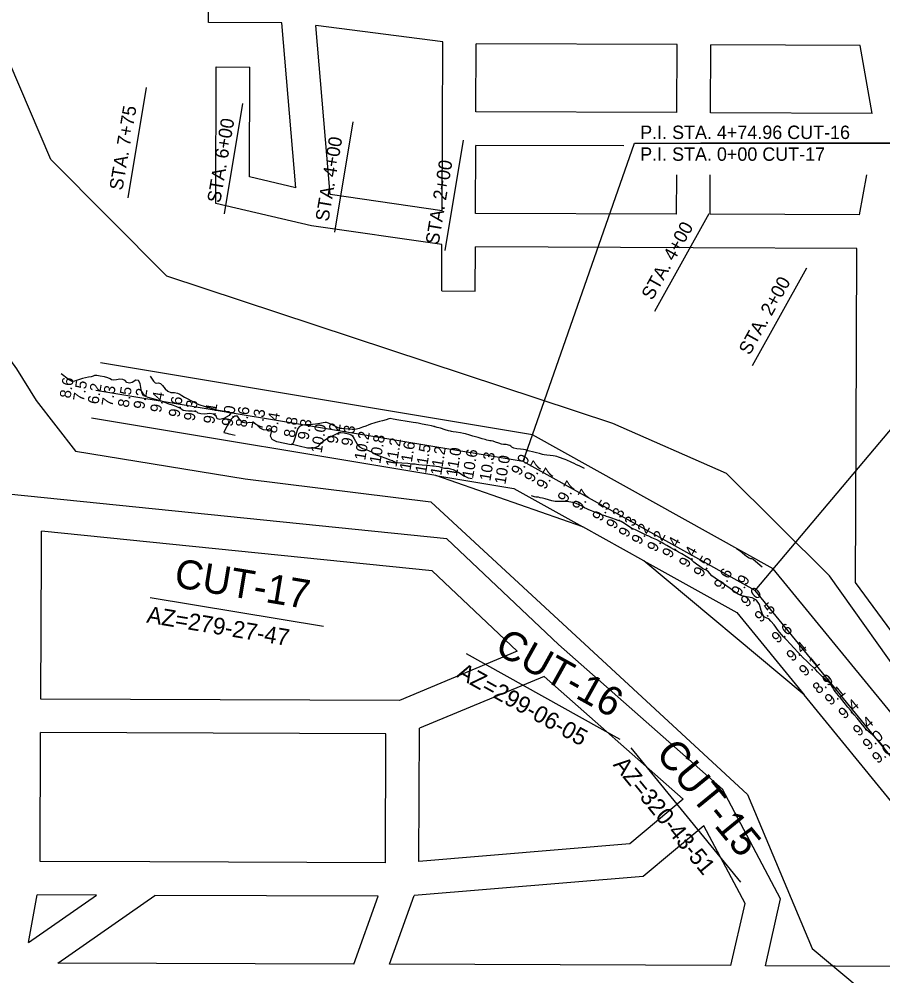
# Model space of a CAD drawing. Extents: x 497696 to 505896, y 1319278 to 1325078.
# Drawn here: x 500990 to 502536, y 1320945 to 1322658 of the extents above; entities that cross this region are included whole.
import ezdxf

# ---------------------------------------------------------------- set-up
doc = ezdxf.new("R2010")
doc.units = 0
for name, color, linetype in [('Level 1', 7, 'Continuous'), ('Level 32', 7, 'Continuous'), ('Level 49', 7, 'Continuous'), ('Level 5', 7, 'Continuous'), ('Level 50', 7, 'Continuous'), ('Level 51', 7, 'Continuous'), ('Level 56', 7, 'Continuous'), ('Level 6', 7, 'Continuous')]:
    doc.layers.add(name, color=color, linetype=linetype)

msp = doc.modelspace()

# ---------------------------------------------------------------- linework, layer by layer
at = {"layer": 'Level 1'}
for points in [[(501212.5, 1321984.1), (501210.3, 1321988.2), (501208.4, 1321995.4), (501206.7, 1322005.8), (501203.5, 1322011.4), (501198.8, 1322012.1), (501192.6, 1322008), (501187.4, 1322006.5), (501183.1, 1322007.6), (501179.9, 1322011.3), (501175.6, 1322013.3), (501170.4, 1322013.6), (501164.2, 1322012.3), (501159.2, 1322012), (501155.5, 1322012.6), (501152.9, 1322014.4), (501148.7, 1322016.1), (501142.8, 1322017.7), (501135.1, 1322019.4), (501129.2, 1322020.2), (501124.9, 1322020.2), (501122.4, 1322019.2), (501118.9, 1322018.2), (501114.4, 1322017.2), (501108.9, 1322016), (501103.5, 1322014.7), (501098.2, 1322013.1), (501092.9, 1322011.4), (501089, 1322010.2), (501086.4, 1322009.5), (501085.2, 1322009.4), (501082.3, 1322010.9), (501077.7, 1322014), (501065.1, 1322023.3)], [(501224.6, 1322019.1), (501230.4, 1322010), (501233.4, 1322007.3), (501236.4, 1322006.4), (501239.4, 1322007.5), (501242.9, 1322006.1), (501246.9, 1322002.5), (501251.3, 1321996.5), (501256.2, 1321992.4), (501261.8, 1321990.2), (501267.9, 1321989.9), (501273.3, 1321988.8), (501277.8, 1321987), (501281.5, 1321984.4), (501286.2, 1321981.5), (501291.8, 1321978.4), (501298.3, 1321975), (501303.3, 1321972.5), (501306.7, 1321970.7), (501308.6, 1321969.7), (501313.4, 1321968.1), (501321, 1321965.7), (501331.4, 1321962.6), (501338.5, 1321960.5), (501342.3, 1321959.3), (501342.8, 1321958.9), (501346.8, 1321958.2), (501354.2, 1321957.1), (501365.1, 1321955.6), (501369.1, 1321952.8), (501366.2, 1321948.8), (501356.4, 1321943.4), (501349.2, 1321941.5), (501344.6, 1321943), (501342.6, 1321947.8), (501338.2, 1321950.9), (501331.4, 1321952.1), (501322.1, 1321951.4), (501315.2, 1321951.6), (501310.7, 1321952.7), (501308.5, 1321954.5), (501304.8, 1321955.8), (501299.6, 1321956.4), (501292.9, 1321956.5), (501287.6, 1321957), (501283.8, 1321957.9), (501281.4, 1321959.3), (501279.4, 1321960.5), (501277.7, 1321961.7), (501276.5, 1321962.7), (501272.6, 1321964.4), (501266.1, 1321966.7), (501257, 1321969.7), (501250.7, 1321971.8), (501247.2, 1321973.2), (501246.4, 1321973.8), (501242.9, 1321975), (501236.5, 1321976.9), (501227.4, 1321979.4), (501221.2, 1321981.1), (501217.9, 1321982.1), (501217.6, 1321982.3), (501216.6, 1321982.7), (501214.9, 1321983.3), (501212.5, 1321984.1)], [(501476.8, 1321896.1), (501451.1, 1321901.6), (501443.1, 1321906), (501440.1, 1321911.9), (501442, 1321919.5), (501441.4, 1321923.8), (501438.5, 1321924.8), (501433.1, 1321922.5), (501427.5, 1321923), (501421.5, 1321926.2), (501415.3, 1321932), (501409, 1321935.5), (501402.7, 1321936.5), (501396.4, 1321935), (501390.6, 1321936.3), (501385.4, 1321940.4), (501380.7, 1321947.3), (501375.4, 1321947.8), (501369.3, 1321942.2), (501362.6, 1321930.2), (501358.3, 1321922.2), (501356.5, 1321918.1), (501357.1, 1321918), (501358.8, 1321917.5), (501361.5, 1321916.9), (501365.3, 1321916), (501368.7, 1321915.2), (501371.6, 1321914.6), (501376.6, 1321913.5)], [(501744, 1321925.8), (501738.2, 1321927.5), (501734.9, 1321928.5), (501734.2, 1321928.7), (501733.5, 1321928.9), (501732.8, 1321929.1), (501732.1, 1321929.3), (501728.3, 1321930.1), (501721.3, 1321931.5), (501711.1, 1321933.5), (501704.2, 1321934.9), (501700.6, 1321935.5), (501700.2, 1321935.5), (501695, 1321936.4), (501684.8, 1321938.1), (501669.9, 1321940.6), (501659.7, 1321942.3), (501654.4, 1321943.1), (501654, 1321943.1), (501651.5, 1321942.5), (501647, 1321941.2), (501640.5, 1321939.2), (501635.2, 1321937.8), (501631.1, 1321936.8), (501628.2, 1321936.3), (501624.7, 1321935.3), (501620.7, 1321933.8), (501616.1, 1321931.9), (501610.8, 1321929.8), (501604.9, 1321927.7), (501598.4, 1321925.5), (501593.7, 1321924.1), (501590.6, 1321923.5), (501589.4, 1321923.6), (501586, 1321923.9), (501580.4, 1321924.3), (501572.7, 1321925), (501567.4, 1321925.3), (501564.4, 1321925.4), (501563.8, 1321925.2), (501561, 1321926.4), (501556.1, 1321928.9), (501549, 1321932.7), (501543.6, 1321935.2), (501540, 1321936.4), (501538, 1321936.1), (501534.1, 1321935.6), (501528.4, 1321934.7), (501520.7, 1321933.5), (501515.4, 1321932.7), (501512.4, 1321932.3), (501511.7, 1321932.3), (501509.7, 1321932.3), (501506.4, 1321932.1), (501501.7, 1321931.8), (501497.7, 1321931.2), (501494.4, 1321930.4), (501491.8, 1321929.3), (501489.1, 1321925.2), (501486.3, 1321918.1), (501483.5, 1321907.9), (501481.1, 1321901.1), (501479.2, 1321897.7), (501477.7, 1321897.7), (501481.7, 1321896.6)], [(501481.7, 1321896.6), (501491.2, 1321894.4), (501506.2, 1321891.1), (501517.8, 1321890.9), (501526, 1321893.8), (501530.8, 1321899.7), (501536.5, 1321904.8), (501543.3, 1321909), (501551, 1321912.5), (501556.7, 1321915.1), (501560.4, 1321917.1), (501562, 1321918.2), (501565.7, 1321918.4), (501571.5, 1321917.7), (501579.3, 1321916.1), (501584.6, 1321914.3), (501587.5, 1321912.3), (501588, 1321910.1), (501589.4, 1321906.9), (501591.8, 1321902.6), (501595.1, 1321897.2), (501599.5, 1321892.9), (501604.9, 1321889.7), (501611.3, 1321887.6), (501616.5, 1321885.5), (501620.5, 1321883.5), (501623.3, 1321881.4), (501628.5, 1321878.9), (501636.1, 1321875.8), (501646.2, 1321872.2), (501653.5, 1321869.6), (501658, 1321867.9), (501659.6, 1321867.1), (501661, 1321866.5), (501662.2, 1321865.8), (501663.2, 1321865.3), (501667.5, 1321864.7), (501675, 1321863.9), (501685.8, 1321863.1), (501693.7, 1321862.4), (501698.8, 1321861.9), (501701.1, 1321861.6), (501705.2, 1321861.1), (501711.1, 1321860.5), (501718.9, 1321859.7), (501725.1, 1321859.1), (501729.7, 1321858.8), (501732.7, 1321858.8), (501736.6, 1321858.3), (501741.3, 1321857.2), (501746.8, 1321855.7), (501751.5, 1321854.7), (501755.2, 1321854.2), (501758.1, 1321854.3), (501761.9, 1321853.5), (501766.6, 1321851.8), (501772.2, 1321849.2), (501777.2, 1321846.5), (501781.8, 1321843.8), (501785.9, 1321840.9), (501789.9, 1321838.8), (501793.7, 1321837.4), (501801.1, 1321835.9)], [(502002.1, 1321854.1), (501992.4, 1321858.4), (501987.8, 1321860.5), (501983.4, 1321862.5), (501979.2, 1321864.5), (501975.6, 1321866.1), (501972.6, 1321867.4), (501970.2, 1321868.5), (501967.2, 1321869.7), (501963.5, 1321871.1), (501959.2, 1321872.8), (501955.5, 1321874.2), (501952.3, 1321875.3), (501949.7, 1321876), (501945.8, 1321876.7), (501940.7, 1321877.4), (501934.4, 1321878), (501929.7, 1321878.6), (501926.6, 1321879.2), (501925.1, 1321879.6), (501921.6, 1321880.5), (501916.2, 1321881.8), (501908.7, 1321883.6), (501903.7, 1321884.8), (501901, 1321885.5), (501900.6, 1321885.7), (501899.7, 1321886), (501898.3, 1321886.5), (501896.2, 1321887.1), (501892.6, 1321887.8), (501887.4, 1321888.5), (501880.7, 1321889.3), (501875.5, 1321890.4), (501872, 1321891.8), (501870, 1321893.6), (501868, 1321894.9), (501865.9, 1321895.9), (501863.9, 1321896.5), (501861.7, 1321896.8), (501859.3, 1321897), (501856.8, 1321896.9), (501853.2, 1321897.6), (501848.6, 1321899), (501842.8, 1321901.1), (501838.2, 1321902.6), (501834.7, 1321903.3), (501832.4, 1321903.4), (501829.9, 1321903.8), (501827.1, 1321904.5), (501824, 1321905.5), (501818.8, 1321907.1), (501811.5, 1321909.3), (501802, 1321912), (501795, 1321914), (501790.6, 1321915.3), (501788.7, 1321916), (501785.1, 1321916.7), (501779.7, 1321917.7), (501772.4, 1321918.8), (501767.1, 1321919.6), (501763.7, 1321920.2), (501762.2, 1321920.5), (501758.4, 1321921.5), (501752.3, 1321923.3), (501744, 1321925.8)], [(502105.1, 1321738.3), (502098.2, 1321741.5), (502093.2, 1321743.8), (502090, 1321745.1), (502088.7, 1321745.5), (502085.8, 1321747.1), (502081.3, 1321749.9), (502075.3, 1321754), (502070.7, 1321757), (502067.5, 1321758.8), (502065.8, 1321759.4), (502062.4, 1321760.7), (502057.4, 1321762.4), (502050.7, 1321764.8), (502045.4, 1321766.7), (502041.4, 1321768), (502038.7, 1321768.9), (502034.4, 1321770.4), (502028.4, 1321772.7), (502020.7, 1321775.6), (502014.4, 1321778.1), (502009.5, 1321780.1), (502005.9, 1321781.7), (502001.9, 1321783.7), (501997.5, 1321786.1), (501992.6, 1321789), (501987, 1321791.2), (501980.8, 1321793), (501973.8, 1321794.2), (501967.3, 1321794.9), (501961.1, 1321795), (501955.2, 1321794.5), (501949.3, 1321794.9), (501943.3, 1321796), (501937.2, 1321797.9), (501931.7, 1321799.4), (501926.9, 1321800.7), (501922.7, 1321801.6), (501919.6, 1321802.3), (501917.5, 1321802.6), (501916.4, 1321802.5), (501914.8, 1321802.8), (501912.5, 1321803.3), (501906.8, 1321804.8)], [(502383.2, 1321525.5), (502377.5, 1321531.7), (502369.7, 1321540.4), (502363.9, 1321546.7), (502360.1, 1321550.7), (502358.3, 1321552.4), (502354.5, 1321556.9), (502348.8, 1321564), (502341.1, 1321573.9), (502335.4, 1321580.7), (502331.7, 1321584.5), (502330, 1321585.3), (502328.1, 1321586.1), (502326, 1321587), (502323.8, 1321587.8), (502321.2, 1321591.9), (502318.4, 1321599.4), (502315.2, 1321610.3), (502309.7, 1321618), (502301.9, 1321622.5), (502291.7, 1321623.9), (502283.3, 1321626), (502276.7, 1321628.6), (502271.9, 1321631.8), (502267.9, 1321634.6), (502264.9, 1321636.9), (502262.7, 1321638.7), (502260.1, 1321640.6), (502257.3, 1321642.8), (502254.1, 1321645), (502249.4, 1321648.2), (502243.3, 1321652.4), (502235.8, 1321657.5), (502230, 1321661.9), (502226.1, 1321665.6), (502223.9, 1321668.7), (502221.6, 1321670.9), (502219.2, 1321672.4), (502216.7, 1321673), (502213, 1321674.9), (502208.2, 1321678.2), (502202.3, 1321682.8), (502197.8, 1321686.3), (502194.8, 1321688.9), (502193.3, 1321690.4), (502189.7, 1321692.9), (502183.9, 1321696.4), (502175.9, 1321701), (502170, 1321704.2), (502166.4, 1321706.3), (502165, 1321707), (502161.6, 1321708.9), (502156.3, 1321712), (502149.1, 1321716.2), (502144, 1321719.2), (502141, 1321721), (502140.2, 1321721.5), (502136.9, 1321723.1), (502131.1, 1321725.9), (502122.7, 1321729.8), (502116.8, 1321732.5), (502113.5, 1321734.1), (502112.7, 1321734.6), (502109.9, 1321735.9), (502105.1, 1321738.3)], [(502274.1, 1321710.3), (502277.3, 1321708.3), (502278.8, 1321707.3), (502280, 1321706.3), (502281, 1321705.4), (502282.1, 1321704.5), (502283.3, 1321703.5), (502284.7, 1321702.5), (502286.1, 1321701.4), (502287.6, 1321700.2), (502289.1, 1321698.8), (502291.1, 1321697.3), (502293.6, 1321695.7), (502296.6, 1321693.9), (502298.9, 1321692.8), (502300.5, 1321692.4), (502301.4, 1321692.8), (502304, 1321691.2), (502308.2, 1321687.9), (502319.8, 1321677.5)], [(502541.4, 1321349.1), (502535.7, 1321357.1), (502529.7, 1321364.5), (502523.3, 1321371.2), (502516.5, 1321377.4), (502511.7, 1321381.7), (502508.9, 1321384.2), (502508.1, 1321384.8), (502507.2, 1321385.6), (502506.4, 1321386.6), (502505.6, 1321387.7), (502502.5, 1321391.4), (502497.2, 1321397.8), (502489.7, 1321406.7), (502484.5, 1321413), (502481.5, 1321416.6), (502480.8, 1321417.6), (502478.1, 1321420.9), (502473.5, 1321426.6), (502466.9, 1321434.7), (502462.4, 1321440.2), (502460, 1321443.1), (502459.8, 1321443.4), (502458.6, 1321444.8), (502456.5, 1321447.3), (502453.5, 1321451), (502450.8, 1321454.6), (502448.2, 1321458.4), (502445.8, 1321462.2), (502444.1, 1321465.1), (502443, 1321466.9), (502442.5, 1321467.9), (502440.6, 1321469.8), (502437.2, 1321472.7), (502432.4, 1321476.7), (502427.7, 1321480.9), (502423.2, 1321485.3), (502418.9, 1321490), (502416, 1321493.2), (502414.4, 1321494.9), (502414.1, 1321495.1), (502411.5, 1321497.6), (502406.5, 1321502.4), (502399.2, 1321509.5), (502394, 1321514.5), (502391, 1321517.4), (502390.2, 1321518.3), (502389.2, 1321519.3), (502388, 1321520.4), (502386.7, 1321521.8), (502383.2, 1321525.5)]]:
    msp.add_lwpolyline(points, dxfattribs=at)
at = {"layer": 'Level 32'}
for p, q in [((501328.7, 1322652.4), (501330.1, 1323009.6)), ((501460.4, 1322651.9), (501328.7, 1322652.4)), ((501485.4, 1322356.6), (501460.4, 1322651.9)), ((501748.2, 1322617.9), (501521, 1322647.3)), ((501546.7, 1322344.4), (501521, 1322647.3)), ((501747.6, 1322462.6), (501748.2, 1322617.9)), ((501807.7, 1322492.4), (501808.2, 1322614.2)), ((502167.8, 1322612.8), (501808.2, 1322614.2)), ((502167.3, 1322491), (502167.8, 1322612.8)), ((502227.3, 1322490.8), (502227.8, 1322612.5)), ((502495.4, 1322611.5), (502227.8, 1322612.5)), ((502516.6, 1322489.6), (502495.4, 1322611.5)), ((501342.9, 1322572.9), (501402.9, 1322572.7)), ((502167.3, 1322491), (501807.7, 1322492.4)), ((502516.6, 1322489.6), (502227.3, 1322490.8)), ((501747, 1322315.4), (501747.6, 1322462.6)), ((501807, 1322310.6), (501807.5, 1322432.4)), ((502072.2, 1322431.4), (501807.5, 1322432.4)), ((502166.6, 1322309.2), (502166.9, 1322379.6)), ((502226.6, 1322309), (502226.9, 1322379.6)), ((502494.3, 1322307.9), (502507.3, 1322379.6)), ((501747, 1322315.4), (501546.7, 1322344.4)), ((502166.6, 1322309.2), (501807, 1322310.6)), ((502494.3, 1322307.9), (502226.6, 1322309)), ((501746.8, 1322254.8), (501513.2, 1322288.6)), ((501746.4, 1322171.8), (501746.8, 1322254.8)), ((501806.4, 1322171.6), (501806.7, 1322250.6)), ((502196.4, 1322249.1), (501806.7, 1322250.6)), ((502489.2, 1322248), (502196.4, 1322249.1)), ((502487.9, 1321914.4), (502489.2, 1322248)), ((501746.4, 1322171.8), (501806.4, 1322171.6)), ((502486.8, 1321650), (502487.9, 1321914.4)), ((501029.9, 1321702), (501030, 1321741.6)), ((501028.9, 1321441.1), (501029.9, 1321702)), ((502939.1, 1321033.8), (502486.8, 1321650)), ((501881.2, 1321526.5), (501670.7, 1321438.6)), ((502248.8, 1321279.9), (501955.5, 1321538.8)), ((501929.5, 1321481.7), (501706.5, 1321388.6)), ((502178.8, 1321261.6), (501929.5, 1321481.7)), ((501670.7, 1321438.6), (501028.9, 1321441.1)), ((501705.6, 1321150.3), (501706.5, 1321388.6)), ((501027.7, 1321150.3), (501028.6, 1321381.1)), ((501646.5, 1321378.7), (501028.6, 1321381.1)), ((501645.6, 1321147.9), (501646.5, 1321378.7)), ((501223.7, 1321149.5), (501027.7, 1321150.3)), ((501645.6, 1321147.9), (501223.7, 1321149.5)), ((501007.1, 1321005), (501022.6, 1321090.3)), ((501007.1, 1321005), (501128.7, 1321089.9)), ((501128.7, 1321089.9), (501022.6, 1321090.3)), ((501059.5, 1320968.4), (501232.9, 1321089.5)), ((501632.9, 1321087.9), (501232.9, 1321089.5)), ((501589.1, 1320966.3), (501632.9, 1321087.9)), ((501652.8, 1320966.1), (501697.2, 1321089.4)), ((501589.1, 1320966.3), (501059.5, 1320968.4)), ((502264.1, 1320963.7), (501652.8, 1320966.1)), ((502606.9, 1320962.3), (502325.6, 1320963.4))]:
    msp.add_line(p, q, dxfattribs=at)
for points in [[(501513.2, 1322288.6), (501341.9, 1322328.3), (501342.9, 1322572.9)], [(501485.4, 1322356.6), (501402.1, 1322375.9), (501402.9, 1322572.7)], [(501955.5, 1321538.8), (501755.5, 1321728), (500970.3, 1321808)], [(501881.2, 1321526.5), (501729.1, 1321670.4), (501030, 1321741.6)], [(502325.6, 1320963.4), (502352.6, 1321083.1), (502248.8, 1321279.9)], [(502178.8, 1321261.6), (502083.3, 1321181.6), (501705.6, 1321150.3)], [(502215.6, 1321214.2), (502107.2, 1321123.4), (501697.2, 1321089.4)], [(502264.1, 1320963.7), (502289.2, 1321074.7), (502215.6, 1321214.2)]]:
    msp.add_lwpolyline(points, dxfattribs=at)
at = {"layer": 'Level 5'}
for points in [[(501677.2, 1324877.9), (501378.4, 1324614.6), (500725.8, 1323766.4), (500625.2, 1323558.4), (500565.9, 1323241.9), (500572.6, 1322708.4), (500738.3, 1322374.6), (500985.2, 1322032), (501020.7, 1321975.5), (501090.8, 1321884.7), (501394.4, 1321835.2), (501726.7, 1321794.1), (502293.5, 1321269.9), (502409.4, 1320994.5), (502987.7, 1320510.5), (503056.9, 1320142.4), (503189.4, 1319858.7), (503438.4, 1319516.2), (503472.5, 1319477.9)], [(504107.7, 1319477.9), (503822.6, 1319798.4), (503531.7, 1320041), (503232.9, 1320458.6), (503199.8, 1320550.4), (502737.7, 1321243.7), (502440.6, 1321661.5), (502255.8, 1321845.1), (502052.9, 1321934.2), (501254.5, 1322198), (501046.8, 1322407), (500972.3, 1322582.2), (500898.1, 1322849.2), (500933, 1323374.1), (501045.4, 1323950.4), (501078.5, 1324015.1), (501460.9, 1324322.7), (501588.1, 1324548.9), (501884.4, 1324877.9)]]:
    msp.add_lwpolyline(points, dxfattribs=at)
at = {"layer": 'Level 50'}
for p, q in [((501908.8, 1321914), (501135.8, 1322042.8)), ((501735.9, 1321841.4), (501119.4, 1321944.2)), ((502339.7, 1321674.1), (501908.8, 1321914)), ((501998.8, 1321749.4), (501735.9, 1321841.4)), ((501735.9, 1321841.4), (501875.3, 1321818.2)), ((501875.3, 1321818.2), (501998.8, 1321749.4)), ((502108, 1321688.7), (501998.8, 1321749.4)), ((502394.9, 1321448.6), (502108, 1321688.7)), ((502108, 1321688.7), (502274.4, 1321596)), ((502644.3, 1321301.7), (502339.7, 1321674.1)), ((502274.4, 1321596), (502394.9, 1321448.6)), ((502563, 1321243.1), (502394.9, 1321448.6))]:
    msp.add_line(p, q, dxfattribs=at)
at = {"layer": 'Level 51'}
for p, q in [((501535.1, 1321570.8), (501224.6, 1321622.5)), ((502065.8, 1321368.8), (501791, 1321521.8)), ((502281.5, 1321113.4), (502085.3, 1321353.4))]:
    msp.add_line(p, q, dxfattribs=at)
at = {"layer": 'Level 56'}
for p, q in [((501185.1, 1322338.7), (501218, 1322536)), ((501357.8, 1322310), (501390.6, 1322507.2)), ((501555, 1322277.1), (501587.9, 1322474.4)), ((501752.3, 1322244.2), (501785.2, 1322441.5)), ((501892.1, 1321866.1), (502091.7, 1322436.3)), ((502091.7, 1322436.3), (502555.6, 1322436.3)), ((502555.6, 1322436.3), (502209.9, 1322436.3)), ((502127.8, 1322135.4), (502225, 1322310.2)), ((502302.5, 1322038.2), (502399.8, 1322212.9)), ((502307.1, 1321635.1), (502688, 1322087.6))]:
    msp.add_line(p, q, dxfattribs=at)
at = {"layer": 'Level 6'}
for p, q in [((501892.1, 1321866.1), (501127.6, 1321993.5)), ((502307.1, 1321635.1), (501892.1, 1321866.1)), ((502603.6, 1321272.4), (502307.1, 1321635.1))]:
    msp.add_line(p, q, dxfattribs=at)

# ---------------------------------------------------------------- texts
at = {"layer": 'Level 49'}
for s, rotation, p in [('8.6', 80.5369, (501081.8, 1321978.5)), ('7.5', 80.5369, (501105.9, 1321973)), ('6.2', 80.5369, (501131.9, 1321968)), ('7.3', 80.5369, (501156.9, 1321964)), ('8.5', 80.5369, (501185.9, 1321962)), ('9.2', 80.5369, (501213.9, 1321959)), ('9.4', 80.5369, (501243.9, 1321953)), ('9.6', 80.5369, (501276.8, 1321944.5)), ('9.3', 80.5369, (501303.9, 1321938)), ('9.1', 80.5369, (501339, 1321932.7)), ('9.0', 80.5369, (501371.7, 1321928.1)), ('8.6', 80.5369, (501396.8, 1321926.5)), ('7.3', 80.5369, (501424.9, 1321922)), ('8.4', 80.5369, (501450.9, 1321916)), ('8.8', 80.5369, (501482.9, 1321908)), ('9.3', 80.5369, (501507.9, 1321904)), ('9.2', 80.5369, (501559.9, 1321897)), ('10.0 ', 80.5369, (501531.4, 1321880.4)), ('9.3', 80.5369, (501585.9, 1321893)), ('10.2 ', 80.5369, (501609.4, 1321867.4)), ('10.8 ', 80.5369, (501636.4, 1321861.4)), ('11.2 ', 80.5369, (501665.4, 1321855.4)), ('11.6 ', 80.5369, (501690.4, 1321849.4)), ('11.5 ', 80.5369, (501718.4, 1321844.4)), ('11.2 ', 80.5369, (501745.4, 1321840.4)), ('11.0 ', 80.5369, (501773.4, 1321838.4)), ('10.6 ', 80.5369, (501802.4, 1321835.4)), ('10.3 ', 80.5369, (501833.4, 1321830.4)), ('10.0 ', 80.5369, (501860.4, 1321824.4)), ('9.9', 60.8986, (501886.6, 1321839.8)), ('9.7', 60.8986, (501909.7, 1321827.9)), ('9.7', 60.8986, (501931.7, 1321814.9)), ('9.7', 60.8986, (501969.7, 1321791.9)), ('9.7', 60.8986, (501995.7, 1321776.9)), ('9.5', 60.8986, (502031.7, 1321757.9)), ('9.3', 60.8986, (502056.7, 1321743.9)), ('9.3', 60.8986, (502078.7, 1321728.9)), ('9.2', 60.8986, (502101.7, 1321715.9)), ('9.2', 60.8986, (502129.7, 1321702.9)), ('9.4', 60.8986, (502156.7, 1321691.9)), ('9.4', 60.8986, (502186.7, 1321674.9)), ('9.5', 60.8986, (502212.7, 1321657.9)), ('9.6', 60.8986, (502249.4, 1321635.4)), ('9.9', 60.8986, (502280.6, 1321623.8)), ('9.0', 39.2692, (502291.7, 1321604.4)), ('9.5', 39.2692, (502316.4, 1321577)), ('9.6', 39.2692, (502346.9, 1321539.6)), ('9.4', 39.2692, (502373.4, 1321507)), ('9.1', 39.2692, (502395.9, 1321480.4)), ('8.9', 39.2692, (502420.3, 1321448.9)), ('9.1', 39.2692, (502441.9, 1321428.4)), ('9.4', 39.2692, (502466.4, 1321404)), ('9.4', 39.2692, (502492.4, 1321373)), ('9.0', 39.2692, (502509.7, 1321348.4)), ('9.0', 39.2692, (502526.7, 1321324.4))]:
    msp.add_text(s, height=20, rotation=rotation, dxfattribs=at).set_placement(p)
at = {"layer": 'Level 51'}
for s, height, rotation, p in [('CUT-17', 52, 350.5369, (501265.7, 1321642)), ('AZ=279-27-47', 30, 350.5369, (501217, 1321578.2)), ('CUT-16', 52, 330.8988, (501838.8, 1321524.9)), ('AZ=299-06-05', 30, 330.8988, (501771.3, 1321481.2)), ('CUT-15', 52, 309.2692, (502127.7, 1321342.6)), ('AZ=320-43-51', 30, 309.2692, (502052, 1321322.9))]:
    msp.add_text(s, height=height, rotation=rotation, dxfattribs=at).set_placement(p)
at = {"layer": 'Level 56'}
for s, rotation, p in [('STA. 7+75', 80.3666, (501174.9, 1322350.9)), ('STA. 6+00', 80.3666, (501350, 1322328.3)), ('STA. 4+00', 80.5952, (501543.8, 1322295.3)), ('STA. 2+00', 80.5375, (501740.8, 1322253.7)), ('STA. 4+00', 60.8901, (502123.3, 1322153.7)), ('STA. 2+00', 60.9292, (502297.5, 1322055.4))]:
    msp.add_text(s, height=24, rotation=rotation, dxfattribs=at).set_placement(p)
for s, p in [('P.I. STA. 4+74.96 CUT-16', (502101.6, 1322443.8)), ('P.I. STA. 0+00 CUT-17', (502101.6, 1322404.8))]:
    msp.add_text(s, height=24, dxfattribs=at).set_placement(p)

doc.saveas('drawing.dxf')
